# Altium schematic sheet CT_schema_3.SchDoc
size 321 x 262 mm
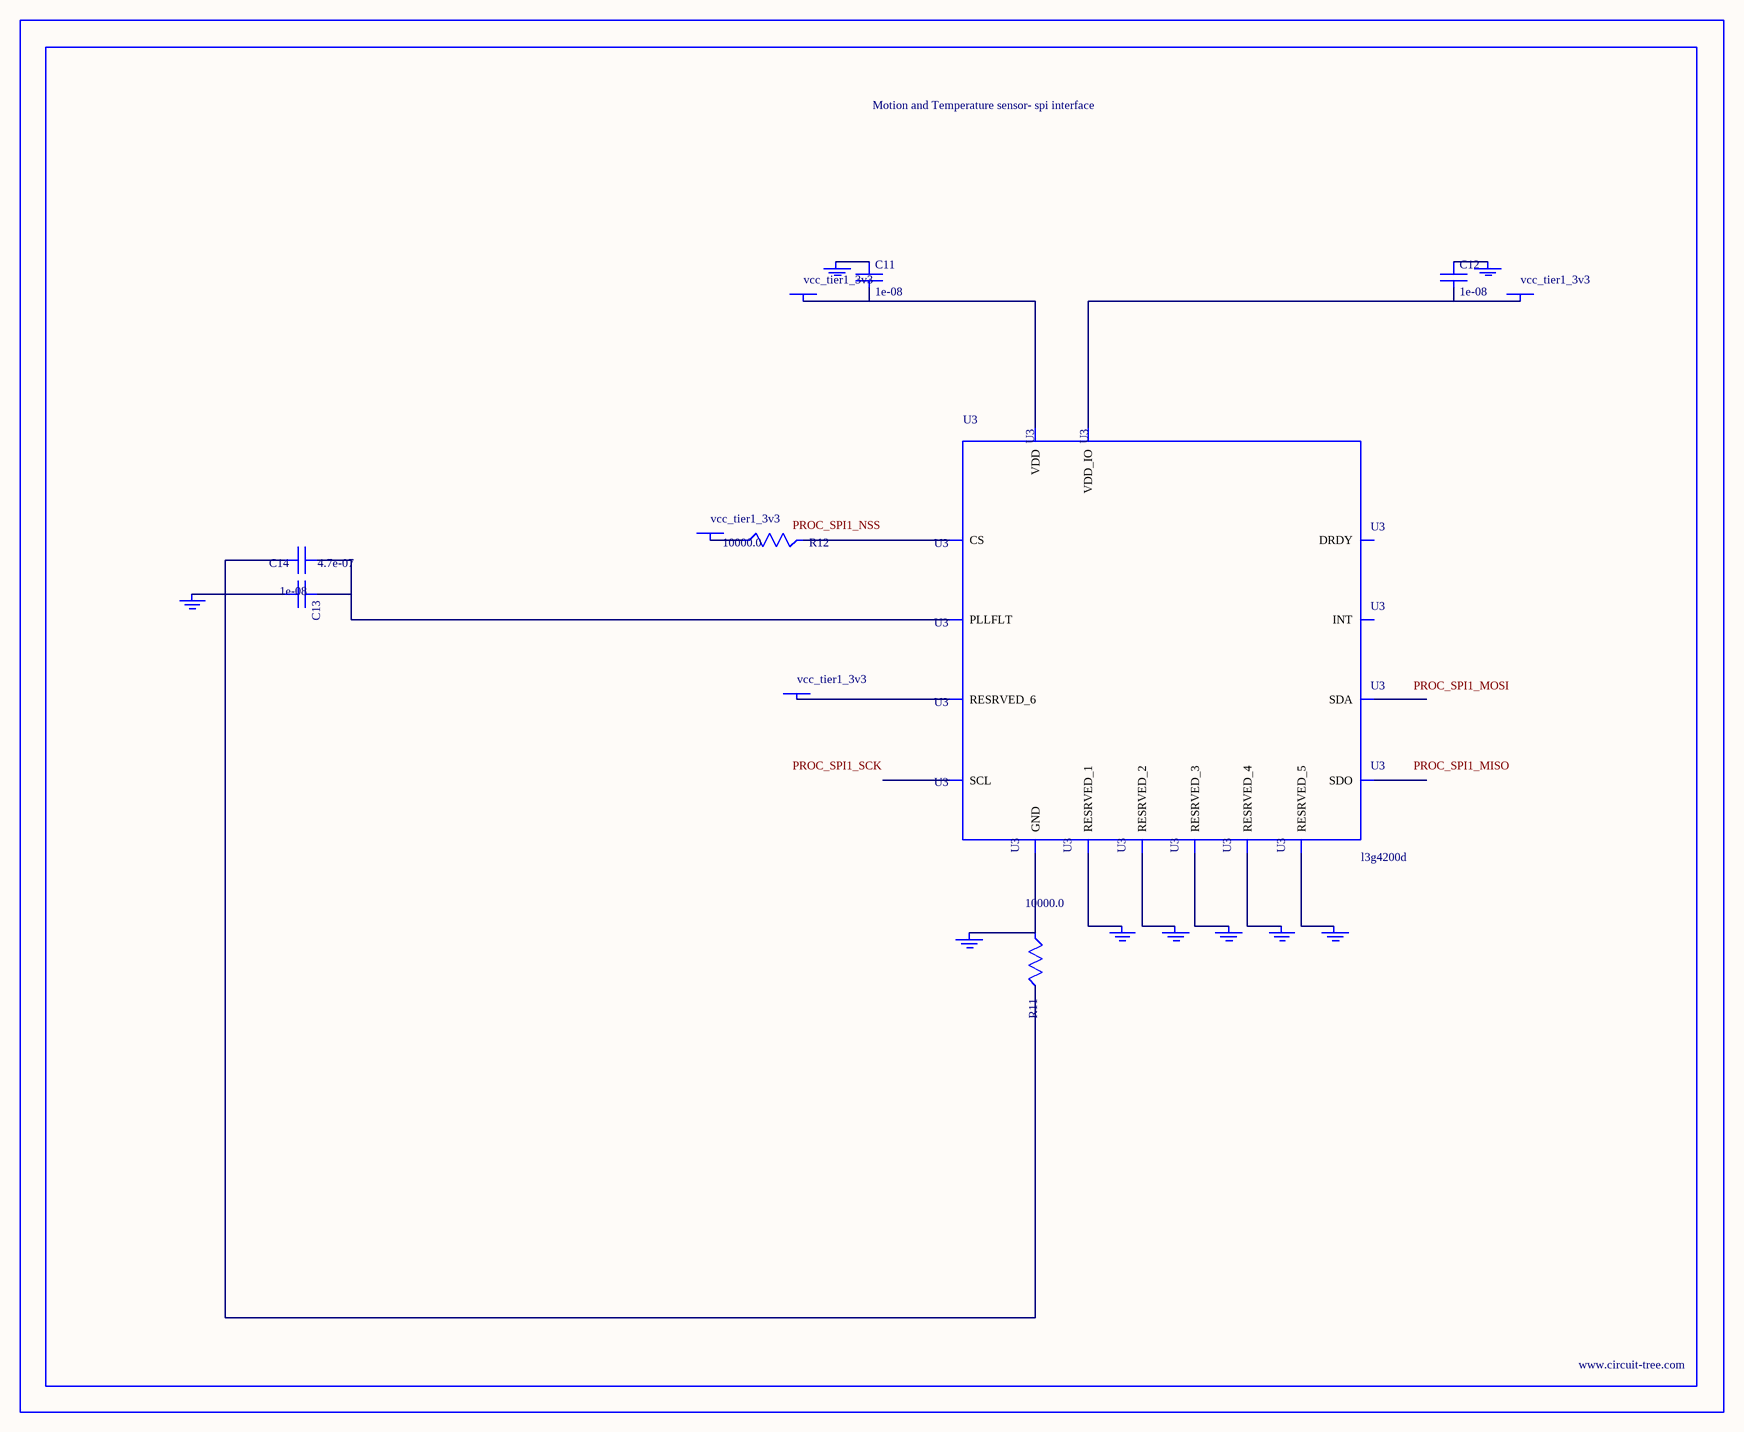
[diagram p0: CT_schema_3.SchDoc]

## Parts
BORDER2  (no value)
C11  1e-08  [C0402]
C12  1e-08  [C0402]
C13  1e-08  [C0402]
C14  4.7e-07  [C0603]
GND_INSTANCE_2_0  (no value)
GND_INSTANCE_2_1  (no value)
GND_INSTANCE_2_2  (no value)
GND_INSTANCE_2_3  (no value)
GND_INSTANCE_2_4  (no value)
GND_INSTANCE_2_5  (no value)
GND_INSTANCE_2_6  (no value)
GND_INSTANCE_2_7  (no value)
GND_INSTANCE_2_8  (no value)
POWER_INSTANCE_2_0  vcc_tier1_3v3
POWER_INSTANCE_2_1  vcc_tier1_3v3
POWER_INSTANCE_2_2  vcc_tier1_3v3
POWER_INSTANCE_2_3  vcc_tier1_3v3
R11  10000.0  [R0603]
R12  10000.0  [R0603]
U3  l3g4200d  [LGA-16]

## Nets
NetC11_1: C11.1 GND_INSTANCE_2_8.0(GND)
NetC11_2: C11.2 POWER_INSTANCE_2_3.0(PWR) U3.16(VDD)
NetC12_1: C12.1 GND_INSTANCE_2_0.0(GND)
NetC12_2: C12.2 POWER_INSTANCE_2_0.0(PWR) U3.1(VDD_IO)
NetC13_1: C13.1 C14.1 U3.14(PLLFLT)
NetC13_2: C13.2 C14.2 GND_INSTANCE_2_7.0(GND) R11.2
NetGND_INSTANCE_2_1_0: GND_INSTANCE_2_1.0(GND) U3.8(RESRVED_1)
NetGND_INSTANCE_2_2_0: GND_INSTANCE_2_2.0(GND) U3.9(RESRVED_2)
NetGND_INSTANCE_2_3_0: GND_INSTANCE_2_3.0(GND) U3.10(RESRVED_3)
NetGND_INSTANCE_2_4_0: GND_INSTANCE_2_4.0(GND) U3.11(RESRVED_4)
NetGND_INSTANCE_2_5_0: GND_INSTANCE_2_5.0(GND) U3.12(RESRVED_5)
NetGND_INSTANCE_2_6_0: GND_INSTANCE_2_6.0(GND) R11.1 U3.13(GND)
NetPOWER_INSTANCE_2_1_0: POWER_INSTANCE_2_1.0(PWR) R12.1
NetPOWER_INSTANCE_2_2_0: POWER_INSTANCE_2_2.0(PWR) U3.15(RESRVED_6)
NetR12_2: R12.2 U3.5(CS)

Not connected (* = marked no-connect by the designer): U3 2(SCL) 3(SDA) 4(SDO) 6(DRDY) 7(INT)

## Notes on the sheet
- Labels drawn without touching a wire or pin: PROC_SPI1_MISO, PROC_SPI1_MOSI, PROC_SPI1_NSS, PROC_SPI1_SCK

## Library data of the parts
BORDER2 = BORDER_PAGE2
C11-C13 = C0402C103K3RAC
C14 = C0603C474K3RAC
GND_INSTANCE_2_0-GND_INSTANCE_2_8 = GND
POWER_INSTANCE_2_0-POWER_INSTANCE_2_3 = PWR
R11 R12 = RC0603JR-0710KL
